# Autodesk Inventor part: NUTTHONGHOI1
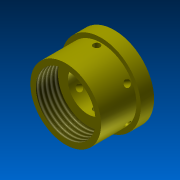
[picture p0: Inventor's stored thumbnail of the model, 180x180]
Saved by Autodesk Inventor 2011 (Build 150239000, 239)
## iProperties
Created: 2011-04
Part Number: NUTTHONGHOI1
Document SubType Name: Modeling
Designer: TRINH
Density: 1 g/cm^3
Mass: 10.9193 g
Surface Area: 59.2132 cm^2
Volume: 10.9193 cm^3
Author: TRINH
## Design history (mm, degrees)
sketch "Sketch1"
  geometry: L1 (0, 0)-(0, -43.486); L2 (18, -1.523)-(18, -7.523); L3 (0, -1.523)-(18, -1.523); L4 (18, -7.523)-(16, -7.523); L5 (16, -7.523)-(16, -23.523); L6 (16, -23.523)-(13.5, -23.523); L7 (13.5, -23.523)-(13.5, -13.523); L8 (13.5, -13.523)-(9, -13.523); L9 (9, -13.523)-(9, -5.523); L10 (9, -5.523)-(0, -5.523); 1 further point
  constraints: 20 end point, 7 perpendicular, 2 parallel, 2 point on line, 1 vertical
  dimensions: "d0" = 6 distance of L2.start L2.end; "d1" = 18 distance between parallel lines of L1 L2; "d2" = 2 distance of L2.end L4.end; "d3" = 16 distance of L4.end L5.end; "d4" = 2.5 distance of L5.end L6.end; "d5" = 10 distance of L6.end L7.end; "d6" = 9 distance from line of L1 L8.end; "d7" = 4 distance from line of L9.end L3; "d19" = 0 horizontal distance of point (0, 0) L3.start; "d21" = 0 distance of L1.start point (0, 0); "d22" = 43.48624 distance of L1.start L1.end; "d23" = 1.52294 distance from line of L1.start L3
revolve "Revolution1" sketch "Sketch1" stored, may be unused: angle "d8" = 90 deg
workplane "Work Plane1"
  workaxis "Work Axis1"
sketch "Sketch2"
  geometry: L1 (-3, -18)-(-3, 18) reference; C1 r 1.5 at (5, 0); 1 further point
  constraints: 1 centre point
  dimensions: "d10" = 8 distance from line of C1.centre L1; "d11" = 3 diameter of C1
extrude "Extrusion1" cut sketch "Sketch2" stored distance "d12" = 10; taper "d13" = 0 deg
pattern_circular "Circular Pattern1" dims angle "d15" = 360 deg
thread "Thread1" dims "d17" = 10, "d18" = 0
body "Solid1"
other parameters: "d9" = 90 deg
